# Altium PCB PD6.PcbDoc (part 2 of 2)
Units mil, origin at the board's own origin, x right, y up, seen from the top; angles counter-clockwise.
Board outline 8543.31 x 5314.96 mil, 4 copper layers (Top Layer, VBAT Plane, GND Plane, Bottom Layer), stack 62.8 mil thick; 258 components, 142 nets, 690 pads, 87 vias.
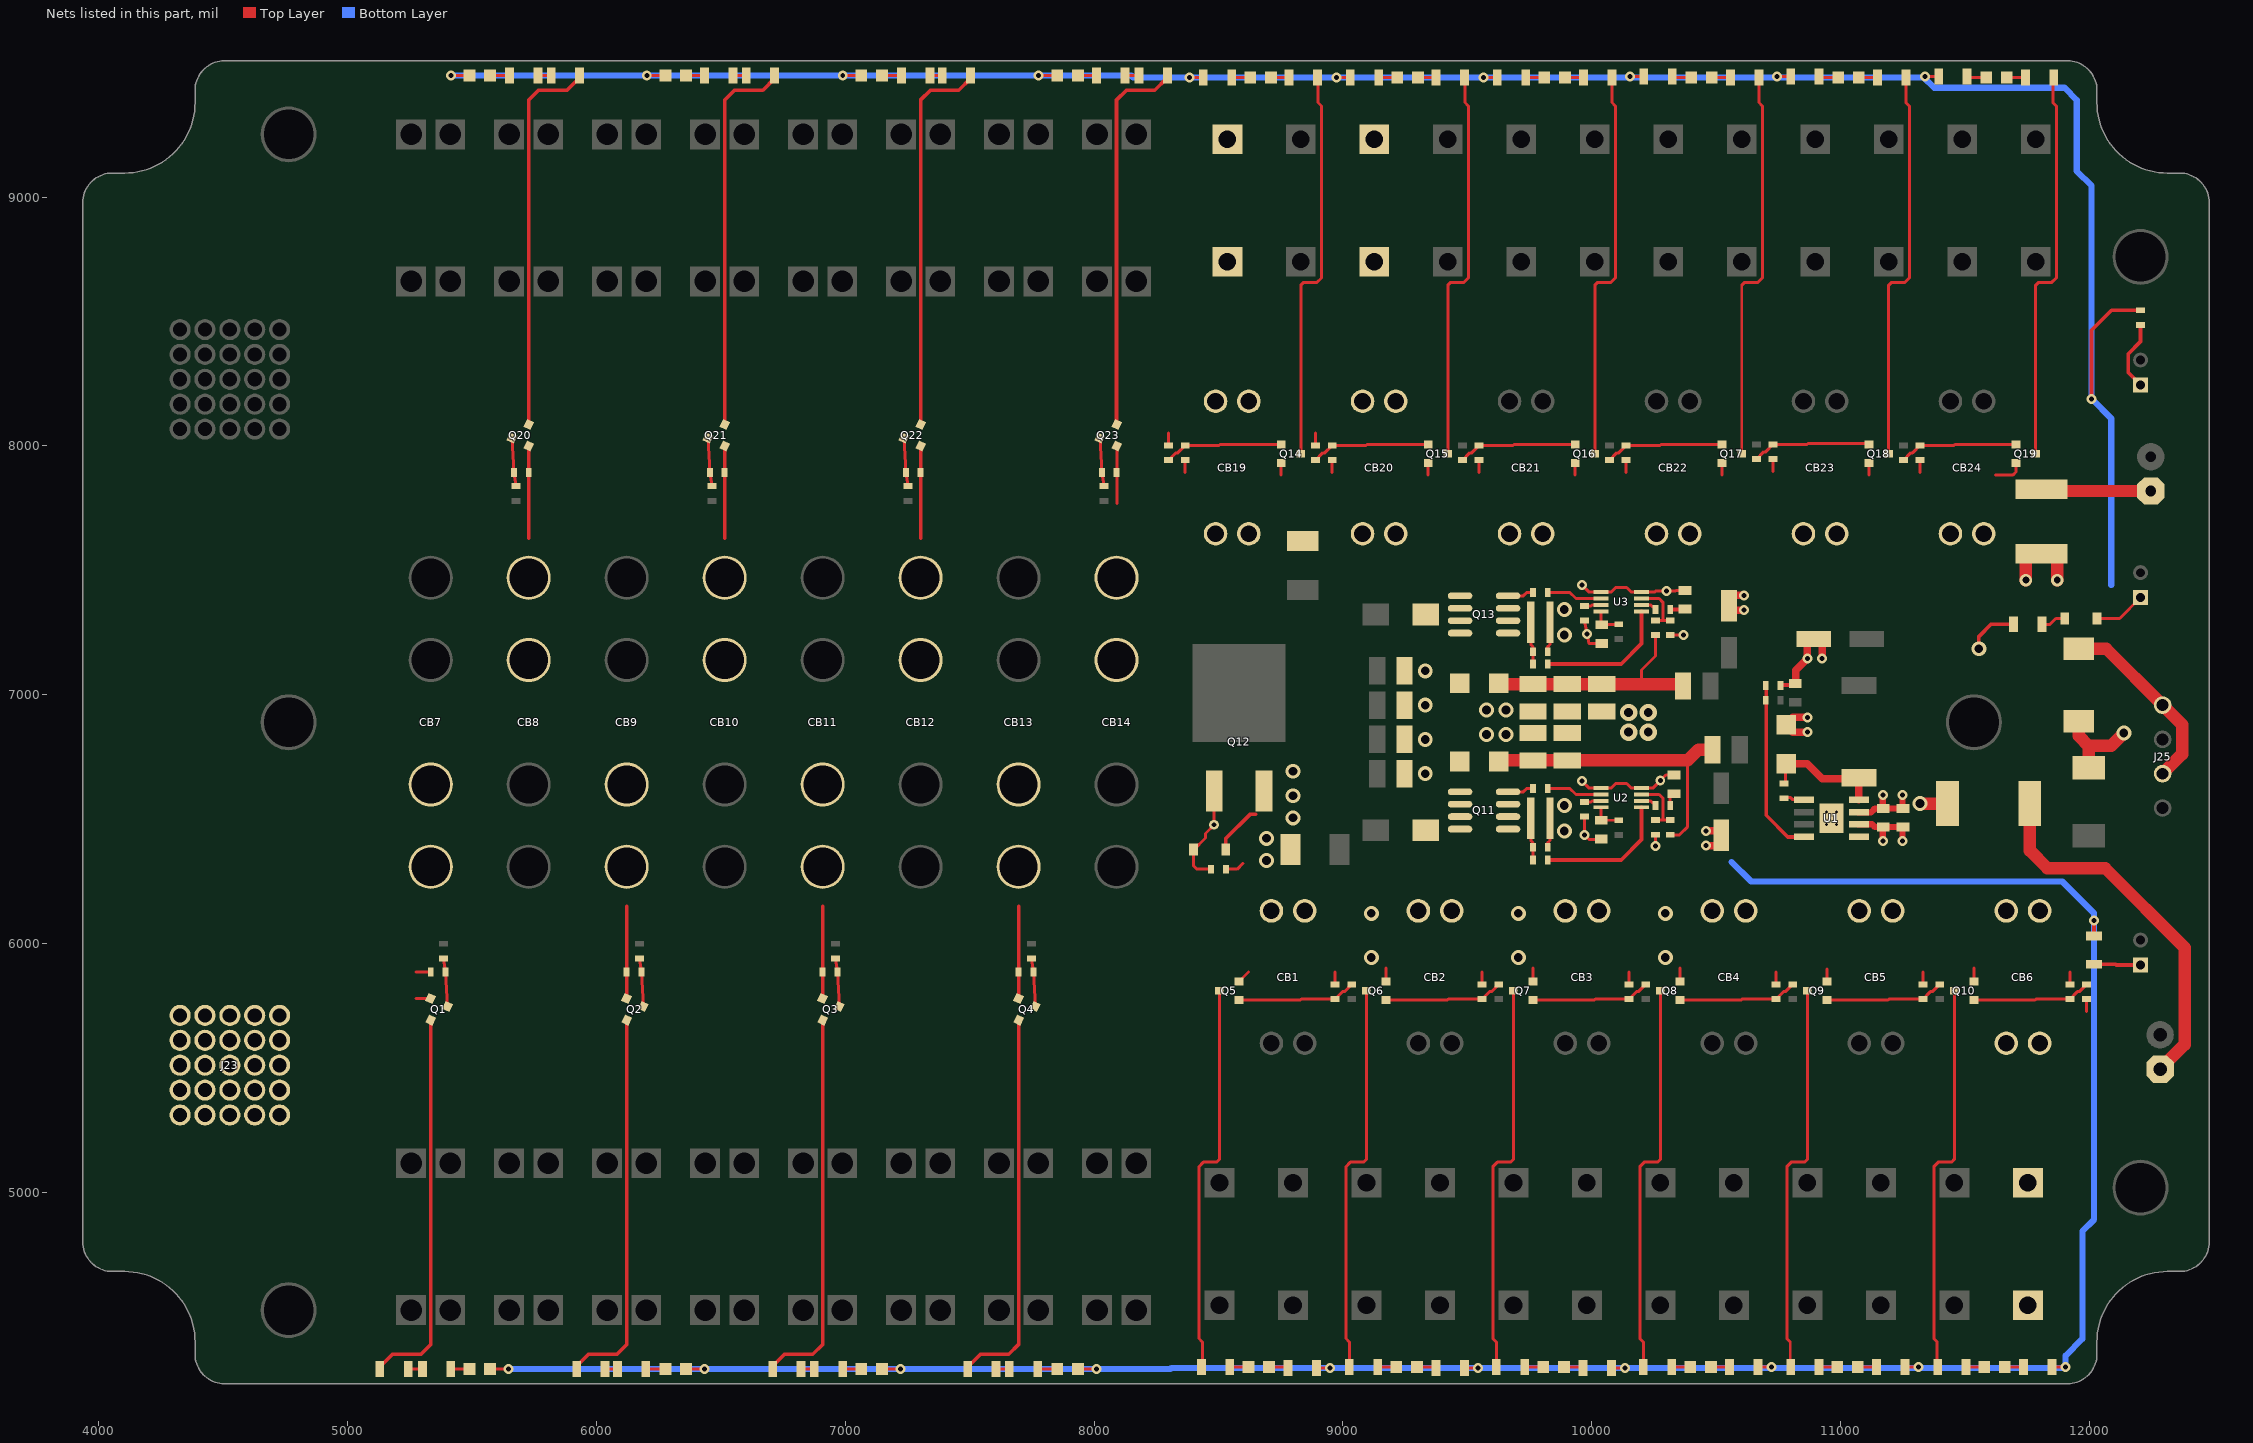
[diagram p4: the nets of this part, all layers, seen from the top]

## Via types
v1: diameter 40, hole 20, Top Layer to Bottom Layer, 47 vias
v2: diameter 60, hole 35, Top Layer to Bottom Layer, 32 vias
v3: diameter 70, hole 35, Top Layer to Bottom Layer, 4 vias
v4: diameter 50, hole 27.99, Top Layer to Bottom Layer, 4 vias

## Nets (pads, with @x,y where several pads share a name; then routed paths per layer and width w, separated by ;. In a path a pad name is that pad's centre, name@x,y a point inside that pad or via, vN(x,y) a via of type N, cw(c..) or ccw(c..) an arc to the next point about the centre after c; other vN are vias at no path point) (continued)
LOWCURRENTOUT_5_2: CB20.2 J39.1 R94.2 | length 49.2
  Top Layer w12: R94.2@8889.76,8001.97 8889.76,8051.18
LOWCURRENTOUT_6_1: CB6.2 J22.1 R101.2 | length 49.2
  Top Layer w12: 11988.19,5728.35 R101.2@11988.19,5777.56
LOWCURRENTOUT_6_2: CB19.2 J37.1 R95.2 | length 49.2
  Top Layer w12: R95.2@8299.21,8001.97 8299.21,8051.18
NetC3_2: C3.2 Q11.S R32.2 R33.2 | length 171
  Top Layer w12: R32.2@9754.92,6503.94 9754.92,6414.37 9763.78,6405.51 C3.2@9763.78,6387.8 R33.2@9763.78,6336.61
NetC4_2: C4.2 R34.1 U2.8 | length 114.2
  Top Layer w12: C4.2@10036.42,6500.98 U2.8@10036.42,6548.23 ; C4.2@10041.34,6496.06 R34.1@10108.27,6496.06
NetC5_1: C5.1 U1.1 | length 89.9
  Top Layer w12: C5.1@10767.72,6586.61 10771.65,6586.61 10799.21,6586.61 10807.09,6578.74 10852.83,6578.74 U1.1@10854.33,6578.74
NetC5_2: C5.2 D13.K L2.1 U1.8 | length 472.9
  Top Layer w12: C5.2@10777.56,6643.7 D13.K@10777.56,6712.6
  Top Layer w25: D13.K@10777.56,6722.44 D13.K@10781.5,6722.44
  Top Layer w30: D13.K@10781.5,6722.44 10866.14,6722.44 10925.2,6663.39 11072.83,6663.39 U1.8@11072.83,6579.13
NetC6_2: C6.2 R37.1 | length 49.9
  Top Layer w12: R37.1@10314.96,6555.12 10314.96,6602.6 10314.96,6604.96 C6.2@10315,6605
NetC8_2: C8.2 C9.2 D12.K L5.1 R40.2 | length 1217
  Top Layer w12: R40.2@10314.8,6437.64 10352.64,6437.64 10385,6470 10385,6736.34
  Top Layer w50: D12.K@9625.98,6736.34 C8.2@9763.78,6736.34 C9.2@9901.57,6736.34 10385,6736.34 10428.66,6780 L5.1@10475,6780
NetC17_2: C17.2 R47.2 U3.8 | length 114.2
  Top Layer w12: C17.2@10036.42,7288.39 U3.8@10036.42,7335.63 ; C17.2@10041.34,7283.46 R47.2@10108.27,7283.46
NetC19_2: C19.2 Q13.S R44.2 R46.2 | length 171
  Top Layer w12: R46.2@9754.92,7291.34 9754.92,7201.77 9763.78,7192.91 C19.2@9763.78,7173.23 R44.2@9763.78,7124.02
NetC20_2: C20.2 R49.1 | length 57.1
  Top Layer w15: R49.1@10314.96,7342.52 C20.2@10372.05,7342.52
NetCB16_2: CB16.2 J24.1 | length 1501.4
  Top Layer w50: CB16.2@11759.84,6562.99 11759.84,6374.02 11830.71,6303.15 12062.99,6303.15 12381.89,5984.25 12381.89,5594.49 J24.1@12283.46,5496.06
NetCB17_2: CB17.2 J25.2 J25.4 | length 771.2
  Top Layer w50: CB17.2@11956.69,7185.04 12066.93,7185.04 J25.4@12293.31,6958.66 12372.05,6879.92 12372.05,6761.81 J25.2@12293.31,6683.07
NetCB25_2: CB25.2 J26.1 | length 442.2
  Top Layer w50: CB25.2@11807.09,7826.77 11814.96,7818.9 J26.1@12246.06,7818.9
NetD1_A: D1.A R2.2 | length 84.6
  Top Layer w12: R2.2@5411.42,4291.34 R2.2@5415.35,4291.34 D1.A@5496.06,4291.34
NetD2_A: D2.A R4.2 | length 84.6
  Top Layer w12: R4.2@6198.82,4291.34 D2.A@6283.46,4291.34
NetD3_A: D3.A R6.2 | length 84.6
  Top Layer w12: R6.2@6986.22,4291.34 R6.2@6990.16,4291.34 D3.A@7070.87,4291.34
NetD4_A: D4.A R8.2 | length 84.6
  Top Layer w12: R8.2@7773.62,4291.34 D4.A@7858.27,4291.34
NetD5_A: D5.A R9.2 | length 76.8
  Top Layer w12: R9.2@8549.21,4299.21 D5.A@8625.98,4299.21
NetD5_K: D5.K R10.1 | length 82.7
  Top Layer w12: D5.K@8696.85,4299.21 R10.1@8779.53,4299.21
NetD6_A: D6.A R11.2 | length 80.7
  Top Layer w12: R11.2@9139.76,4299.21 D6.A@9220.47,4299.21
NetD6_K: D6.K R12.1 | length 78.7
  Top Layer w12: D6.K@9291.34,4299.21 R12.1@9370.08,4299.21
NetD7_A: D7.A R13.2 | length 80.7
  Top Layer w12: R13.2@9730.32,4299.21 D7.A@9811.02,4299.21
NetD7_K: D7.K R14.1 | length 78.7
  Top Layer w12: D7.K@9881.89,4299.21 R14.1@9960.63,4299.21
NetD8_A: D8.A R15.2 | length 80.7
  Top Layer w12: R15.2@10320.87,4299.21 D8.A@10401.57,4299.21
NetD8_K: D8.K R16.1 | length 78.7
  Top Layer w12: D8.K@10472.44,4299.21 R16.1@10551.18,4299.21
NetD9_A: D9.A R17.2 | length 80.7
  Top Layer w12: R17.2@10911.42,4299.21 R17.2@10913.39,4299.21 D9.A@10992.13,4299.21
NetD9_K: D9.K R18.1 | length 78.7
  Top Layer w12: D9.K@11062.99,4299.21 R18.1@11141.73,4299.21
NetD10_A: D10.A R19.2 | length 80.7
  Top Layer w12: R19.2@11501.97,4299.21 R19.2@11503.94,4299.21 D10.A@11582.68,4299.21
NetD10_K: D10.K R20.1 | length 78.7
  Top Layer w12: D10.K@11653.54,4299.21 R20.1@11732.28,4299.21
NetD11_K: D11.K R21.2 | length 188.1
  Top Layer w15: R21.2@12017.72,5917.32 12104.33,5917.32 12107.09,5914.57 D11.K@12204.72,5914.57
NetD12_A: D12.A L1.1 Q11.D
NetD14_K: D14.K D16.K | length 210.4
  Top Layer w12: D16.K@12029.06,7307.09 12120.87,7307.09 D14.K@12204.72,7390.94
NetD15_A: D15.A L3.1 Q13.D
NetD16_A: D16.A R35.2 | length 100.8
  Top Layer w12: R35.2@11809.06,7283.46 11840.55,7283.46 11864.17,7307.09 D16.A@11900.08,7307.09
NetD17_K: D17.K R61.2 | length 282.1
  Top Layer w15: D17.K@12204.72,8245.28 12155,8295 12155,8370 12204.72,8419.72 R61.2@12204.72,8486.22
NetD18_A: D18.A R62.2 | length 84.6
  Top Layer w12: D18.A@5566.93,9488.19 R62.2@5651.57,9488.19
NetD19_A: D19.A R64.2 | length 84.6
  Top Layer w12: D19.A@6354.33,9488.19 R64.2@6435.04,9488.19 R64.2@6438.98,9488.19
NetD20_A: D20.A R66.2 | length 84.6
  Top Layer w12: D20.A@7141.73,9488.19 R66.2@7226.38,9488.19
NetD21_A: D21.A R68.2 | length 84.6
  Top Layer w12: D21.A@7929.13,9488.19 R68.2@8009.84,9488.19 R68.2@8013.78,9488.19
NetD22_A: D22.A R71.2 | length 80.7
  Top Layer w12: D22.A@8704.72,9480.32 R71.2@8783.46,9480.31 R71.2@8785.43,9480.32
NetD22_K: D22.K R70.1 | length 78.7
  Top Layer w12: R70.1@8555.12,9480.32 D22.K@8633.86,9480.32
NetD23_A: D23.A R73.2 | length 80.7
  Top Layer w12: D23.A@9295.28,9480.32 R73.2@9374.02,9480.31 R73.2@9375.98,9480.32
NetD23_K: D23.K R72.1 | length 78.7
  Top Layer w12: R72.1@9145.67,9480.32 D23.K@9224.41,9480.32
NetD24_A: D24.A R75.2 | length 80.7
  Top Layer w12: D24.A@9885.83,9480.32 R75.2@9966.54,9480.31
NetD24_K: D24.K R74.1 | length 78.7
  Top Layer w12: R74.1@9736.22,9480.32 D24.K@9814.96,9480.32
NetD25_A: D25.A R77.2 | length 80.7
  Top Layer w12: D25.A@10476.38,9480.32 R77.2@10557.09,9480.32
NetD25_K: D25.K R76.1 | length 78.7
  Top Layer w12: R76.1@10326.77,9480.32 D25.K@10405.51,9480.32
NetD26_A: D26.A R79.2 | length 80.7
  Top Layer w12: D26.A@11066.93,9480.32 R79.2@11147.64,9480.31
NetD26_K: D26.K R78.1 | length 78.7
  Top Layer w12: R78.1@10917.32,9480.32 D26.K@10996.06,9480.32
NetD27_A: D27.A R81.2 | length 76.8
  Top Layer w12: D27.A@11661.42,9480.32 R81.2@11738.19,9480.32
NetD27_K: D27.K R80.1 | length 82.7
  Top Layer w12: R80.1@11507.87,9480.32 D27.K@11590.55,9480.32
NetD28_K: D28.K Q12.G R102.1 | length 411.8
  Top Layer w12: R102.1@8470.47,6299.21 8413.39,6299.21 8400.08,6312.52 D28.K@8400.08,6377.95 8447.32,6425.2 8447.32,6442.6 v1(8482.68,6477.95) Q12.G@8482.68,6614.17
NetQ1_D: Q1.D R1.1 | length 1539.6
  Top Layer w15: R1.1@5133.86,4303.15 5181.1,4350.39 5295.28,4350.39 5334.65,4389.76 Q1.D@5334.65,5692.67
NetQ1_G: Q1.G R22.2 R82.1 | length 193.5
  Top Layer w12: R82.1@5385.83,5940.94 R22.2@5393.7,5885.83 Q1.G@5401.82,5748.22
NetQ2_D: Q2.D R3.1 | length 1539.6
  Top Layer w15: R3.1@5921.26,4303.15 5968.5,4350.39 6082.68,4350.39 6122.05,4389.76 Q2.D@6122.05,5692.67
NetQ2_G: Q2.G R23.2 R83.1 | length 193.5
  Top Layer w12: R83.1@6173.23,5940.94 R23.2@6181.1,5885.83 Q2.G@6189.22,5748.22
NetQ3_D: Q3.D R5.1 | length 1539.6
  Top Layer w15: R5.1@6708.66,4303.15 6755.91,4350.39 6870.08,4350.39 6909.45,4389.76 Q3.D@6909.45,5692.67
NetQ3_G: Q3.G R24.2 R84.1 | length 193.5
  Top Layer w12: R84.1@6960.63,5940.94 R24.2@6968.5,5885.83 Q3.G@6976.62,5748.22
NetQ4_D: Q4.D R7.1 | length 1539.6
  Top Layer w15: R7.1@7496.06,4303.15 7543.31,4350.39 7657.48,4350.39 7696.85,4389.76 Q4.D@7696.85,5692.67
NetQ4_G: Q4.G R25.2 R85.1 | length 193.5
  Top Layer w12: R85.1@7748.03,5940.94 R25.2@7755.91,5885.83 Q4.G@7764.02,5748.22
NetQ5_D: Q5.D R9.1 | length 1582.9
  Top Layer w12: R9.1@8431.1,4299.21 8435.04,4299.21 8435.04,4399.61 8421.26,4413.39 8421.26,5104.33 8438.98,5122.05 8492.13,5122.05 8503.94,5133.86 Q5.D@8503.94,5807.09
NetQ5_G: Q5.G R26.2 R96.1 | length 478.8
  Top Layer w12: Q5.G@8582.68,5773.62 8828.74,5773.62 8832.68,5777.56 R26.2@8968.5,5777.56 8998.03,5807.09 9005.91,5807.09 R96.1@9035.43,5836.61
NetQ6_D: Q6.D R11.1 | length 1579
  Top Layer w12: R11.1@9025.59,4299.21 9025.59,4399.61 9011.81,4413.39 9011.81,5104.33 9029.53,5122.05 9082.68,5122.05 9094.49,5133.86 Q6.D@9094.49,5807.09
NetQ6_G: Q6.G R27.2 R97.1 | length 478.8
  Top Layer w12: Q6.G@9173.23,5773.62 9419.29,5773.62 9423.23,5777.56 R27.2@9559.06,5777.56 9588.58,5807.09 9596.46,5807.09 R97.1@9625.98,5836.61
NetQ7_D: Q7.D R13.1 | length 1579
  Top Layer w12: R13.1@9616.14,4299.21 9616.14,4399.61 9602.36,4413.39 9602.36,5104.33 9620.08,5122.05 9673.23,5122.05 9685.04,5133.86 Q7.D@9685.04,5807.09
NetQ7_G: Q7.G R28.2 R98.1 | length 478.8
  Top Layer w12: Q7.G@9763.78,5773.62 10009.84,5773.62 10013.78,5777.56 R28.2@10149.61,5777.56 10179.13,5807.09 10187.01,5807.09 R98.1@10216.54,5836.61
NetQ8_D: Q8.D R15.1 | length 1579
  Top Layer w12: R15.1@10206.69,4299.21 10206.69,4399.61 10192.91,4413.39 10192.91,5104.33 10210.63,5122.05 10263.78,5122.05 10275.59,5133.86 Q8.D@10275.59,5807.09
NetQ8_G: Q8.G R29.2 R99.1 | length 478.8
  Top Layer w12: Q8.G@10354.33,5773.62 10600.39,5773.62 10604.33,5777.56 R29.2@10740.16,5777.56 10769.68,5807.09 10777.56,5807.09 R99.1@10807.09,5836.61
NetQ9_D: Q9.D R17.1 | length 1579
  Top Layer w12: R17.1@10797.24,4299.21 10797.24,4399.61 10783.46,4413.39 10783.46,5104.33 10801.18,5122.05 10854.33,5122.05 10866.14,5133.86 Q9.D@10866.14,5807.09
NetQ9_G: Q9.G R30.2 R100.1 | length 478.8
  Top Layer w12: Q9.G@10944.88,5773.62 11190.94,5773.62 11194.88,5777.56 R30.2@11330.71,5777.56 11360.24,5807.09 11368.11,5807.09 R100.1@11397.64,5836.61
NetQ10_D: Q10.D R19.1 | length 1579
  Top Layer w12: R19.1@11387.8,4299.21 11387.8,4399.61 11374.02,4413.39 11374.02,5104.33 11391.73,5122.05 11444.88,5122.05 11456.69,5133.86 Q10.D@11456.69,5807.09
NetQ10_G: Q10.G R31.2 R101.1 | length 478.8
  Top Layer w12: Q10.G@11535.43,5773.62 11781.5,5773.62 11785.43,5777.56 R31.2@11921.26,5777.56 11950.79,5807.09 11958.66,5807.09 R101.1@11988.19,5836.61
NetQ11_G: Q11.G R38.2 | length 106
  Top Layer w12: Q11.G@9663.39,6610.43 9724.61,6610.43 9738.19,6624.02 R38.2@9763.78,6624.02
NetQ13_G: Q13.G R50.2 | length 106
  Top Layer w12: Q13.G@9663.39,7397.83 9724.61,7397.83 9738.19,7411.42 R50.2@9763.78,7411.42
NetQ14_D: Q14.D R71.1 | length 1579
  Top Layer w12: Q14.D@8830.71,7972.44 8830.71,8645.67 8842.52,8657.48 8895.67,8657.48 8913.39,8675.2 8913.39,9366.14 8899.61,9379.92 R71.1@8899.61,9480.31
NetQ14_G: Q14.G R55.2 R95.1 | length 478.8
  Top Layer w12: R95.1@8299.21,7942.91 8328.74,7972.44 8336.61,7972.44 R55.2@8366.14,8001.97 8501.97,8001.97 8505.91,8005.91 Q14.G@8751.97,8005.91
NetQ15_D: Q15.D R73.1 | length 1579
  Top Layer w12: Q15.D@9421.26,7972.44 9421.26,8645.67 9433.07,8657.48 9486.22,8657.48 9503.94,8675.2 9503.94,9366.14 9490.16,9379.92 R73.1@9490.16,9480.31
NetQ15_G: Q15.G R56.2 R94.1 | length 478.8
  Top Layer w12: R94.1@8889.76,7942.91 8919.29,7972.44 8927.17,7972.44 R56.2@8956.69,8001.97 9092.52,8001.97 9096.46,8005.91 Q15.G@9342.52,8005.91
NetQ16_D: Q16.D R75.1 | length 1579
  Top Layer w12: Q16.D@10011.81,7972.44 10011.81,8645.67 10023.62,8657.48 10076.77,8657.48 10094.49,8675.2 10094.49,9366.14 10080.71,9379.92 R75.1@10080.71,9480.31
NetQ16_G: Q16.G R57.2 R93.1 | length 478.8
  Top Layer w12: R93.1@9480.32,7942.91 9509.84,7972.44 9517.72,7972.44 R57.2@9547.24,8001.97 9683.07,8001.97 9687.01,8005.91 Q16.G@9933.07,8005.91
NetQ17_D: Q17.D R77.1 | length 1579
  Top Layer w12: Q17.D@10602.36,7972.44 10602.36,8645.67 10614.17,8657.48 10667.32,8657.48 10685.04,8675.2 10685.04,9366.14 10671.26,9379.92 R77.1@10671.26,9480.32
NetQ17_G: Q17.G R58.2 R92.1 | length 478.8
  Top Layer w12: R92.1@10070.87,7942.91 10100.39,7972.44 10108.27,7972.44 R58.2@10137.8,8001.97 10273.62,8001.97 10277.56,8005.91 Q17.G@10523.62,8005.91
NetQ18_D: Q18.D R79.1 | length 1579
  Top Layer w12: Q18.D@11192.91,7972.44 11192.91,8645.67 11204.72,8657.48 11257.87,8657.48 11275.59,8675.2 11275.59,9366.14 11261.81,9379.92 R79.1@11261.81,9480.31
NetQ18_G: Q18.G R59.2 R91.1 | length 478.8
  Top Layer w12: R91.1@10661.42,7946.85 10690.94,7976.38 10698.82,7976.38 R59.2@10728.35,8005.91 10864.17,8005.91 10868.11,8009.84 Q18.G@11114.17,8009.84
NetQ19_D: Q19.D R81.1 | length 1582.9
  Top Layer w12: Q19.D@11783.46,7972.44 11783.46,8645.67 11795.28,8657.48 11848.43,8657.48 11866.14,8675.2 11866.14,9366.14 11852.36,9379.92 11852.36,9480.31 R81.1@11856.3,9480.32
NetQ19_G: Q19.G R60.2 R90.1 | length 478.8
  Top Layer w12: R90.1@11251.97,7942.91 11281.5,7972.44 11289.37,7972.44 R60.2@11318.9,8001.97 11454.72,8001.97 11458.66,8005.91 Q19.G@11704.72,8005.91
NetQ20_D: Q20.D R63.1 | length 1539.6
  Top Layer w15: Q20.D@5728.35,8086.86 5728.35,9389.76 5767.72,9429.13 5881.89,9429.13 R63.1@5929.13,9476.38
NetQ20_G: Q20.G R51.2 R89.1 | length 193.5
  Top Layer w12: Q20.G@5661.17,8031.31 R51.2@5669.29,7893.7 R89.1@5677.17,7838.58
NetQ21_D: Q21.D R65.1 | length 1539.6
  Top Layer w15: Q21.D@6515.75,8086.86 6515.75,9389.76 6555.12,9429.13 6669.29,9429.13 R65.1@6716.54,9476.38
NetQ21_G: Q21.G R52.2 R88.1 | length 193.5
  Top Layer w12: Q21.G@6448.57,8031.31 R52.2@6456.69,7893.7 R88.1@6464.57,7838.58
NetQ22_D: Q22.D R67.1 | length 1539.6
  Top Layer w15: Q22.D@7303.15,8086.86 7303.15,9389.76 7342.52,9429.13 7456.69,9429.13 R67.1@7503.94,9476.38
NetQ22_G: Q22.G R53.2 R87.1 | length 193.5
  Top Layer w12: Q22.G@7235.98,8031.31 R53.2@7244.09,7893.7 R87.1@7251.97,7838.58
NetQ23_D: Q23.D R69.1 | length 1539.6
  Top Layer w15: Q23.D@8090.55,8086.86 8090.55,9389.76 8129.92,9429.13 8244.09,9429.13 R69.1@8291.34,9476.38
NetQ23_G: Q23.G R54.2 R86.1 | length 193.5
  Top Layer w12: Q23.G@8023.38,8031.31 R54.2@8031.5,7893.7 R86.1@8039.37,7838.58
NetR1_2: R1.2 R2.1 | length 53.1
  Top Layer w12: R1.2@5244.09,4291.34 R2.1@5297.24,4291.34
NetR3_2: R3.2 R4.1 | length 53.1
  Top Layer w12: R3.2@6031.5,4291.34 R3.2@6035.43,4291.34 R4.1@6084.65,4291.34
NetR5_2: R5.2 R6.1 | length 53.1
  Top Layer w12: R5.2@6818.9,4291.34 R5.2@6822.83,4291.34 R6.1@6872.05,4291.34
NetR7_2: R7.2 R8.1 | length 53.1
  Top Layer w12: R7.2@7606.3,4291.34 R8.1@7659.45,4291.34
NetR33_1: R33.1 U2.1 | length 540.7
  Top Layer w15: R33.1@9822.83,6336.61 10118.11,6336.61 10199.8,6418.31 U2.1@10199.8,6548.23
NetR36_2: R36.2 U2.7 | length 67.6
  Top Layer w12: R36.2@9970.47,6569.88 9997.05,6569.88 10000.98,6573.82 U2.7@10036.42,6573.82
NetR37_2: R37.2 U2.2 | length 63.8
  Top Layer w12: U2.2@10199.8,6573.82 10237.2,6573.82 R37.2@10255.91,6555.12
NetR38_1: R38.1 U2.6 | length 223.8
  Top Layer w12: R38.1@9822.83,6624.02 9911.42,6624.02 9936.02,6599.41 U2.6@10036.42,6599.41
NetR39_2: R39.2 R40.1 U2.3 | length 238.5
  Top Layer w12: U2.3@10199.8,6599.41 10270.59,6599.41 10285,6585 10285,6496.69 ; R39.2@10255.75,6496.69 10285,6496.69 ; R40.1@10314.8,6496.69 10285,6496.69
NetR41_1: R41.1 R42.2 U3.3 | length 223.6
  Top Layer w12: U3.3@10199.8,7386.81 10270.67,7386.81 10285.43,7372.05 10285.43,7299.21 ; R41.1@10255.91,7299.21 10285.43,7299.21 ; R42.2@10314.96,7299.21 10285.43,7299.21
NetR43_1: R43.1 R45.2 U1.4 | length 709.1
  Top Layer w15: R45.2@10700.79,7035.43 10700.79,6978.35 10700.79,6515.75 10787.4,6429.13 U1.4@10852.83,6429.13 U1.4@10854.33,6429.13
NetR44_1: R44.1 U3.1 | length 540.7
  Top Layer w15: R44.1@9822.83,7124.02 10118.11,7124.02 10199.8,7205.71 U3.1@10199.8,7335.63
NetR48_2: R48.2 U3.7 | length 67.6
  Top Layer w12: R48.2@9970.47,7357.28 9997.05,7357.28 10000.98,7361.22 U3.7@10036.42,7361.22
NetR49_2: R49.2 U3.2 | length 63.8
  Top Layer w12: U3.2@10199.8,7361.22 10237.2,7361.22 R49.2@10255.91,7342.52
NetR50_1: R50.1 U3.6 | length 223.8
  Top Layer w12: R50.1@9822.83,7411.42 9911.42,7411.42 9936.02,7386.81 U3.6@10036.42,7386.81
NetR62_1: R62.1 R63.2 | length 53.1
  Top Layer w12: R62.1@5765.75,9488.19 R63.2@5818.9,9488.19
NetR64_1: R64.1 R65.2 | length 53.1
  Top Layer w12: R64.1@6553.15,9488.19 R65.2@6602.36,9488.19 R65.2@6606.3,9488.19
NetR66_1: R66.1 R67.2 | length 53.1
  Top Layer w12: R66.1@7340.55,9488.19 R67.2@7389.76,9488.19 R67.2@7393.7,9488.19
NetR68_1: R68.1 R69.2 | length 53.1
  Top Layer w12: R68.1@8127.95,9488.19 R69.2@8181.1,9488.19
NetU1_5: U1.5
"OUTPUT VOLTAGE": C11.2 C12.2 C14.2 D15.K L4.1 R41.2 | length 954.9
  Top Layer w12: 10200,7043.19 10200,7100 10255.91,7155.91 R41.2@10255.91,7240.16
  Top Layer w50: D15.K@9625.98,7043.19 C14.2@9763.78,7043.19 C11.2@9901.57,7043.19 C12.2@10039.37,7043.19 10200,7043.19 10358.19,7043.19 10358.35,7043.35 L4.1@10360,7045
PSGND: C1.1 C2.1 C3.1 C4.1 C6.1 C7.1 C8.1 C9.1 C10.1 C11.1 C12.1 C13.1 C14.1 C15.1 C16.1 C17.1 C18.- C19.1 C20.1 C21.- C22.- CB16.1 CB17.1 CB25.1 D1.K D2.K D3.K D4.K D13.A D18.K D19.K D20.K D21.K D28.A D30.A Q12.S R10.2 R12.2 R14.2 R16.2 R18.2 R20.2 R21.1 R32.1 R35.1 R36.1 R39.1 R42.1 R45.1 R46.1 R48.1 R61.1 R70.2 R72.2 R74.2 R76.2 R78.2 R80.2 U1.6 U1.PAD U2.4 U2.5 U3.4 U3.5 | length 27983.5
  Top Layer w12: v1(5415.35,9488.19) D18.K@5490.16,9488.19 D18.K@5496.06,9488.19 ; D1.K@5566.93,4291.34 D1.K@5572.83,4291.34 v1(5647.64,4291.34) ; v1(6202.76,9488.19) D19.K@6277.56,9488.19 D19.K@6283.46,9488.19 ; D2.K@6354.33,4291.34 D2.K@6360.24,4291.34 v1(6435.04,4291.34) ; v1(6990.16,9488.19) D20.K@7064.96,9488.19 D20.K@7070.87,9488.19 ; D3.K@7141.73,4291.34 D3.K@7147.64,4291.34 v1(7222.44,4291.34) ; v1(7777.56,9488.19) D21.K@7852.36,9488.19 D21.K@7858.27,9488.19 ; D4.K@7929.13,4291.34 D4.K@7935.04,4291.34 v1(8009.84,4291.34) ; v1(8383.86,9480.32) R70.2@8437.01,9480.32 ; R70.2@8437.01,9488.19 R70.2@8437.01,9480.32 ; R70.2@8438.98,9480.31 R70.2@8437.01,9480.32 ; R10.2@8893.7,4295.28 R10.2@8897.64,4295.28 ; R10.2@8897.64,4287.4 R10.2@8897.64,4295.28 ; v1(8948.82,4295.28) R10.2@8897.64,4295.28 ; v1(8974.41,9480.31) R72.2@9027.56,9480.32 ; R72.2@9027.56,9488.19 R72.2@9027.56,9480.32 ; R72.2@9029.53,9480.31 R72.2@9027.56,9480.32 ; R12.2@9488.19,4287.4 R12.2@9488.19,4295.28 v1(9543.31,4295.28) ; v1(9564.96,9480.32) R74.2@9618.11,9480.32 ; R74.2@9618.11,9488.19 R74.2@9618.11,9480.32 ; R74.2@9620.08,9480.32 R74.2@9618.11,9480.32 ; C3.1@9822.83,6385.83 C3.1@9822.83,6387.8 9822.83,6405.51 9831.69,6414.37 R32.1@9831.69,6503.94 ; C19.1@9822.83,7173.23 9822.83,7192.91 9831.69,7201.77 R46.1@9831.69,7291.34 ; v1(9960.63,6653.54) 9989.17,6625 U2.5@10036.42,6625 10077.26,6625 10095.96,6643.7 10140.26,6643.7 10158.96,6625 U2.4@10199.8,6625 10245,6625 v1(10275,6655) 10297.4,6677.4 C6.1@10330,6677.4 ; v1(9960.63,7440.94) 9989.17,7412.4 U3.5@10036.42,7412.4 10077.26,7412.4 10095.96,7431.1 10140.26,7431.1 10158.96,7412.4 U3.4@10199.8,7412.4 10251.97,7412.4 10255.91,7416.34 v1(10300.2,7416.34) 10334.65,7416.34 10337.6,7419.29 C20.1@10374.02,7419.29 ; R36.1@9970.47,6510.83 v1(9970.47,6437.01) 9988.19,6419.29 10037.4,6419.29 C4.1@10039.37,6419.29 ; R48.1@9970.47,7298.23 v1(9980.32,7244.09) 9988.19,7206.69 C17.1@10039.37,7206.69 ; R14.2@10078.74,4287.4 R14.2@10078.74,4295.28 v1(10133.86,4295.28) ; v1(10153.54,9484.25) R76.2@10208.66,9484.25 R76.2@10208.66,9492.13 ; v1(10255.75,6392.36) R39.1@10255.75,6437.64 ; R42.1@10314.96,7240.16 v1(10369.09,7240.16) ; R16.2@10667.32,4299.21 R16.2@10669.29,4299.21 ; R16.2@10669.29,4291.34 R16.2@10669.29,4299.21 ; v1(10722.44,4299.21) R16.2@10669.29,4299.21 ; v1(10744.09,9484.25) R78.2@10799.21,9484.25 R78.2@10799.21,9492.13 ; R18.2@11257.87,4299.21 R18.2@11259.84,4299.21 ; R18.2@11259.84,4291.34 R18.2@11259.84,4299.21 ; v1(11312.99,4299.21) R18.2@11259.84,4299.21 ; v1(11338.58,9484.25) R80.2@11389.76,9484.25 ; R80.2@11389.76,9492.13 R80.2@11389.76,9484.25 ; R80.2@11393.7,9484.25 R80.2@11389.76,9484.25 ; R20.2@11848.43,4299.21 R20.2@11850.39,4299.21 ; R20.2@11850.39,4291.34 R20.2@11850.39,4299.21 ; v1(11903.54,4299.21) R20.2@11850.39,4299.21
  Top Layer w15: D28.A@8529.06,6377.95 8529.06,6422.49 8626.25,6519.69 8649.61,6519.69 ; R45.1@10759.84,7039.37 C15.1@10803.15,7039.37 ; v2(11555.12,7185.04) 11555.12,7234.25 11604.33,7283.46 R35.1@11694.88,7283.46 ; v1(12007.87,8188.98) 12007.87,8464.57 12088.58,8545.28 R61.1@12204.72,8545.28 ; R21.1@12017.72,6031.5 v1(12017.72,6092.52)
  Top Layer w25: U1.6@11070.87,6480.31 11072.83,6480.31 11125.98,6480.31 11137.8,6468.5 C1.1@11171.26,6468.5 11248.03,6468.5 v1(11248.03,6413.39) ; v1(11169.29,6413.39) C1.1@11169.29,6468.5
  Top Layer w30: v1(10458.86,6394.25) 10517.91,6394.25 C22.-@10533.68,6410.02 ; v1(10458.86,6453.31) 10517.91,6453.31 10527.85,6443.37 C22.-@10533.76,6437.46 ; C21.-@10553.27,7340.47 v1(10612.32,7340.47) ; C21.-@10553.27,7399.53 v1(10612.32,7399.53) ; D13.A@10787.4,6870.08 10807.09,6850.39 v1(10866.14,6850.39) ; D13.A@10787.4,6889.76 10807.09,6909.45 v1(10866.14,6909.45) ; C15.1@10818.9,7047.24 10818.9,7098.43 v1(10866.14,7145.67) C18.-@10866.14,7204.72 ; v1(10925.2,7145.67) C18.-@10925.2,7204.72
  Top Layer w50: v2(11318.9,6562.99) CB16.1@11429.13,6562.99 ; CB25.1@11742.13,7568.9 11744.09,7566.93 v4(11744.09,7460.63) ; v4(11870.08,7460.63) 11870.08,7566.93 CB25.1@11870.08,7568.9 ; CB17.1@11956.69,6893.7 11956.69,6834.65 11996.06,6795.28 ; D30.A@11996.06,6707.68 11996.06,6795.28 ; v2(12137.8,6846.46) 12086.61,6795.28 11996.06,6795.28
  Bottom Layer w25: v1(5415.35,9488.19) v1(6202.76,9488.19) v1(6990.16,9488.19) v1(7777.56,9488.19) 8149.61,9488.19 8157.48,9480.32 v1(8383.86,9480.32) ; v1(5647.64,4291.34) v1(6435.04,4291.34) v1(7222.44,4291.34) v1(8009.84,4291.34) 8307.09,4291.34 8311.02,4295.28 v1(8948.82,4295.28) v1(9543.31,4295.28) v1(10133.86,4295.28) ; 10561.02,6328.74 10639.76,6250 11889.76,6250 12017.72,6122.05 v1(12017.72,6092.52) 12017.72,4891.73 11970.96,4844.98 11970.96,4411.91 11903.54,4344.49 v1(11903.54,4299.21) 11899.61,4295.28 11312.99,4295.28 v1@10722.44,4295.28 ; 12086.61,7440.94 12086.61,8110.24 v1(12007.87,8188.98) 12007.87,9045.28 11948.82,9104.33 11948.82,9389.76 11899.61,9438.98 11375.98,9438.98 11334.65,9480.32 10744.09,9480.32 v1@10153.54,9480.32 ; v1(8383.86,9480.32) v1(8974.41,9480.31) ; v1(8383.86,9480.32) v1(8974.41,9480.31) ; v1(8383.86,9480.32) v1(8974.41,9480.31) ; v1(8383.86,9480.32) v1(8974.41,9480.31) ; v1(8974.41,9480.31) v1(9564.96,9480.32) ; v1(8974.41,9480.31) v1(9564.96,9480.32) ; v1(8974.41,9480.31) v1(9564.96,9480.32) ; v1(9564.96,9480.32) v1@10153.54,9480.32 ; v1(9564.96,9480.32) v1@10153.54,9480.32 ; v1(10133.86,4295.28) v1@10722.44,4295.28 ; v1(10133.86,4295.28) v1@10722.44,4295.28
  other v2: 9889.76,6452.76 8799.21,6505.91 9889.76,6555.12 8799.21,6594.49 9330.71,6683.07 8799.21,6692.91 9330.71,6820.87 9576.77,6840.55 9655.51,6840.55 9576.77,6938.98 9655.51,6938.98 9330.71,6958.66 9330.71,7096.46 9889.76,7240.16 9889.76,7342.52
  other v3: 10147.64,6850.39 10226.38,6850.39 10147.64,6929.13 10226.38,6929.13
VBAT: C1.2 C2.2 CB1.1 CB2.1 CB3.1 CB4.1 CB5.1 CB6.1 CB7.1 CB8.1 CB9.1 CB10.1 CB11.1 CB12.1 CB13.1 CB14.1 CB15.2 CB18.2 CB19.1 CB20.1 CB21.1 CB22.1 CB23.1 CB24.1 J23.PAD Q1.S Q2.S Q3.S Q4.S Q5.S Q6.S Q7.S Q8.S Q9.S Q10.S Q14.S Q15.S Q16.S Q17.S Q18.S Q19.S Q20.S Q21.S Q22.S Q23.S R22.1 R23.1 R24.1 R25.1 R26.1 R27.1 R28.1 R29.1 R30.1 R31.1 R51.1 R52.1 R53.1 R54.1 R55.1 R56.1 R57.1 R58.1 R59.1 R60.1 R102.2 U1.7 | length 4425.7
  Top Layer w12: 5275.28,5779.83 Q1.S@5334.03,5779.83 ; 5275.59,5885.83 R22.1@5334.65,5885.83 ; 8091.17,7768.34 8091.17,7893.7 Q23.S@8091.17,7999.69 ; 8366.14,7893.7 R55.1@8366.14,7942.91 ; R102.2@8529.53,6299.21 8574.8,6299.21 8598.43,6322.83 ; Q5.S@8582.68,5848.43 8620.26,5886.01 ; 8751.97,7883.86 Q14.S@8751.97,7931.1 Q14.S@8751.97,7935.04 ; 8956.69,7893.7 R56.1@8956.69,7942.91 ; R26.1@8968.5,5836.61 8968.5,5885.83 ; Q6.S@9173.23,5848.43 9173.23,5901.57 ; 9342.52,7883.86 Q15.S@9342.52,7931.1 Q15.S@9342.52,7935.04 ; 9547.24,7893.7 R57.1@9547.24,7942.91 ; R27.1@9559.06,5836.61 9559.06,5885.83 ; Q7.S@9763.78,5848.43 9763.78,5901.57 ; 9933.07,7883.86 Q16.S@9933.07,7931.1 Q16.S@9933.07,7935.04 ; 10137.8,7893.7 R58.1@10137.8,7942.91 ; R28.1@10149.61,5836.61 10149.61,5885.83 ; Q8.S@10354.33,5848.43 10354.33,5901.57 ; 10523.62,7883.86 Q17.S@10523.62,7931.1 Q17.S@10523.62,7935.04 ; 10728.35,7897.64 R59.1@10728.35,7946.85 ; R29.1@10740.16,5836.61 10740.16,5885.83 ; Q9.S@10944.88,5848.43 10944.88,5897.64 ; 11114.17,7883.86 Q18.S@11114.17,7931.1 Q18.S@11114.17,7935.04 ; 11318.9,7893.7 R60.1@11318.9,7942.91 ; R30.1@11330.71,5836.61 11330.71,5885.83 ; Q10.S@11535.43,5848.43 11535.43,5901.57 ; 11622.87,7883.86 11692.91,7883.86 11704.72,7895.67 Q19.S@11704.72,7931.1 Q19.S@11704.72,7935.04 ; R31.1@11921.26,5836.61 11921.26,5885.83
  Top Layer w15: 5728.35,7629.92 5728.35,7736.22 R51.1@5728.35,7893.7 Q20.S@5728.35,7999.69 ; Q2.S@6122.05,5779.53 6122.05,5779.83 R23.1@6122.05,5885.83 6122.05,6043.31 6122.05,6149.61 ; 6515.75,7629.92 R52.1@6515.75,7893.7 ; Q21.S@6515.75,7999.69 Q21.S@6515.75,7992.13 ; Q3.S@6909.45,5779.53 6909.45,5779.83 Q3.S@6909.45,5787.4 ; 6909.45,6149.61 R24.1@6909.45,5885.83 ; 7303.15,7629.92 7303.15,7736.22 R53.1@7303.15,7893.7 Q22.S@7303.15,7999.69 ; Q4.S@7696.85,5779.53 7696.85,5779.83 R25.1@7696.85,5885.83 7696.85,6043.31 7696.85,6149.61 ; R52.1@6515.75,7893.7 Q21.S@6515.75,7992.13 ; R52.1@6515.75,7893.7 Q21.S@6515.75,7992.13 ; Q3.S@6909.45,5787.4 R24.1@6909.45,5885.83 ; Q3.S@6909.45,5787.4 R24.1@6909.45,5885.83
  Top Layer w25: U1.7@11070.87,6527.56 11072.83,6527.56 11122.05,6527.56 11137.8,6543.31 C1.2@11171.26,6543.31 11248.03,6543.31 v1(11248.03,6598.43) ; C1.2@11169.29,6543.31 v1(11169.29,6598.43)
  other v2: 9114.17,5944.88 9704.72,5944.88 10295.28,5944.88 9114.17,6122.05 9704.72,6122.05 10295.28,6122.05 8692.91,6334.65 8692.91,6423.23
pads on no net: U1.2 U1.3

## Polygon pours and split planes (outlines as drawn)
VBAT on Top Layer "Top Layer-No Net" (solid, remove dead copper, pour order 1008): 8582.68,6259.84 11929.13,6259.84 11929.13,5870.08 8582.68,5870.08
VBAT on Top Layer "Top Layer-VBAT 1" (solid, remove dead copper, pour order 1007): 8257.87,7519.69 11669.29,7519.69 11669.29,7909.45 8257.87,7909.45 8257.87,7519.69
HIGHCURRENTOUT_3_2 on Top Layer "Top Layer-VBAT" (solid, remove dead copper, pour order 1020): 6338.58,7480.31 6338.58,7047.24 6299.21,7007.87 5944.88,7007.87 5905.51,7047.24 5905.51,7480.31 5748.03,7637.8 5748.03,8425.2 5905.51,8582.68 5905.51,9370.08 5944.88,9409.45 6299.21,9409.45 6338.58,9370.08 6338.58,8582.68 6496.06,8425.2 6496.06,7637.8
HIGHCURRENTOUT_2_2 on Top Layer "Top Layer-VBAT" (solid, remove dead copper, pour order 1019): 7125.98,7480.31 7125.98,7047.24 7086.61,7007.87 6732.28,7007.87 6692.91,7047.24 6692.91,7480.31 6535.43,7637.8 6535.43,8425.2 6692.91,8582.68 6692.91,9370.08 6732.28,9409.45 7086.61,9409.45 7125.98,9370.08 7125.98,8582.68 7283.46,8425.2 7283.46,7637.8
HIGHCURRENTOUT_1_2 on Top Layer "Top Layer-VBAT" (solid, remove dead copper, pour order 1018): 7913.39,7480.31 7913.39,7047.24 7874.02,7007.87 7519.69,7007.87 7480.31,7047.24 7480.31,7480.31 7322.83,7637.8 7322.83,8425.2 7480.31,8582.68 7480.31,9370.08 7519.69,9409.45 7874.02,9409.45 7913.39,9370.08 7913.39,8582.68 8070.87,8425.2 8070.87,7637.8
HIGHCURRENTOUT_4_2 on Top Layer "Top Layer-VBAT" (solid, remove dead copper, pour order 1014): 5551.18,7480.31 5551.18,7047.24 5511.81,7007.87 5157.48,7007.87 5118.11,7047.24 5118.11,7480.31 5039.37,7559.06 5039.37,8503.94 5118.11,8582.68 5118.11,9370.08 5157.48,9409.45 5511.81,9409.45 5551.18,9370.08 5551.18,8582.68 5708.66,8425.2 5708.66,7637.8
NetC3_2 on Top Layer "Top Layer-GND" (solid, remove dead copper, pour order 1000): 9566.93,6299.21 9734.25,6299.21 9734.25,6427.17 9812.99,6427.17 9812.99,6594.49 9606.3,6594.49 9566.93,6594.49
NetC19_2 on Top Layer "Top Layer-GND" (solid, remove dead copper, pour order 1002): 9566.93,7086.61 9734.25,7086.61 9734.25,7214.57 9812.99,7214.57 9812.99,7381.89 9606.3,7381.89 9566.93,7381.89
24_VIN on Top Layer "Top Layer-GND" (solid, remove dead copper, pour order 1001): 8858.27,7480.31 8858.27,6999.61 ccw(c8958.27,6999.61) 8958.27,6899.61 9183.07,6899.61 9183.07,7480.31
12_VIN on Top Layer "Top Layer-GND" (solid, remove dead copper, pour order 1003): 8858.27,6299.21 8858.27,6779.92 cw(c8958.27,6779.92) 8958.27,6879.92 9183.07,6879.92 9183.07,6299.21
HIGHCURRENTOUT_1_1 on Top Layer "Top Layer-VBAT" (solid, remove dead copper, pour order 1022): 5511.81,6299.21 5511.81,6732.28 5551.18,6771.65 5905.51,6771.65 5944.88,6732.28 5944.88,6299.21 6102.36,6141.73 6102.36,5354.33 5944.88,5196.85 5944.88,4409.45 5905.51,4370.08 5551.18,4370.08 5511.81,4409.45 5511.81,5196.85 5354.33,5354.33 5354.33,6141.73
HIGHCURRENTOUT_2_1 on Top Layer "Top Layer-VBAT" (solid, remove dead copper, pour order 1009): 6299.21,6299.21 6299.21,6732.28 6338.58,6771.65 6692.91,6771.65 6732.28,6732.28 6732.28,6299.21 6889.76,6141.73 6889.76,5354.33 6732.28,5196.85 6732.28,4409.45 6692.91,4370.08 6338.58,4370.08 6299.21,4409.45 6299.21,5196.85 6141.73,5354.33 6141.73,6141.73
HIGHCURRENTOUT_3_1 on Top Layer "Top Layer-VBAT" (solid, remove dead copper, pour order 1010): 7086.61,6299.21 7086.61,6732.28 7125.98,6771.65 7480.31,6771.65 7519.69,6732.28 7519.69,6299.21 7677.17,6141.73 7677.17,5354.33 7519.69,5196.85 7519.69,4409.45 7480.31,4370.08 7125.98,4370.08 7086.61,4409.45 7086.61,5196.85 6929.13,5354.33 6929.13,6141.73
HIGHCURRENTOUT_4_1 on Top Layer "Top Layer-VBAT" (solid, remove dead copper, pour order 1012): 7874.02,6299.21 7874.02,6732.28 7913.39,6771.65 8267.72,6771.65 8307.09,6732.28 8307.09,6299.21 8464.57,6141.73 8464.57,5354.33 8307.09,5196.85 8307.09,4409.45 8267.72,4370.08 7913.39,4370.08 7874.02,4409.45 7874.02,5196.85 7716.54,5354.33 7716.54,6141.73
VBAT on Top Layer "Top Layer-VBAT HP" (solid, remove dead copper, pour order 1023): 3838.58,7677.17 7913.39,7677.17 7913.39,7913.39 8257.87,7913.39 8257.87,6102.36 5511.81,6102.36 5511.81,4409.45 5000,4409.45 5000,4133.86 3838.58,4133.86
HIGHCURRENTOUT_2_1 on Bottom Layer "Top Layer-VBAT" (solid, remove dead copper, pour order 1004): 6299.21,6299.21 6299.21,6732.28 6338.58,6771.65 6692.91,6771.65 6732.28,6732.28 6732.28,6299.21 6889.76,6141.73 6889.76,5354.33 6732.28,5196.85 6732.28,5039.37 6692.91,5000 6338.58,5000 6299.21,5039.37 6299.21,5196.85 6141.73,5354.33 6141.73,6141.73
HIGHCURRENTOUT_3_1 on Bottom Layer "Top Layer-VBAT" (solid, remove dead copper, pour order 1006): 7086.61,6299.21 7086.61,6732.28 7125.98,6771.65 7480.31,6771.65 7519.69,6732.28 7519.69,6299.21 7677.17,6141.73 7677.17,5354.33 7519.69,5196.85 7519.69,5039.37 7480.31,5000 7125.98,5000 7086.61,5039.37 7086.61,5196.85 6929.13,5354.33 6929.13,6141.73
HIGHCURRENTOUT_4_1 on Bottom Layer "Top Layer-VBAT" (solid, remove dead copper, pour order 1011): 7874.02,6299.21 7874.02,6732.28 7913.39,6771.65 8267.72,6771.65 8307.09,6732.28 8307.09,6299.21 8464.57,6141.73 8464.57,5354.33 8307.09,5196.85 8307.09,5039.37 8267.72,5000 7913.39,5000 7874.02,5039.37 7874.02,5196.85 7716.54,5354.33 7716.54,6141.73
HIGHCURRENTOUT_4_2 on Bottom Layer "Top Layer-VBAT" (solid, remove dead copper, pour order 1013): 5551.18,7480.31 5551.18,7047.24 5511.81,7007.87 5157.48,7007.87 5118.11,7047.24 5118.11,7480.31 5039.37,7559.06 5039.37,8503.94 5118.11,8582.68 5118.11,8740.16 5157.48,8779.53 5511.81,8779.53 5551.18,8740.16 5551.18,8582.68 5708.66,8425.2 5708.66,7637.8
HIGHCURRENTOUT_3_2 on Bottom Layer "Top Layer-VBAT" (solid, remove dead copper, pour order 1015): 6338.58,7480.31 6338.58,7047.24 6299.21,7007.87 5944.88,7007.87 5905.51,7047.24 5905.51,7480.31 5748.03,7637.8 5748.03,8425.2 5905.51,8582.68 5905.51,8740.16 5944.88,8779.53 6299.21,8779.53 6338.58,8740.16 6338.58,8582.68 6496.06,8425.2 6496.06,7637.8
HIGHCURRENTOUT_2_2 on Bottom Layer "Top Layer-VBAT" (solid, remove dead copper, pour order 1016): 7125.98,7480.31 7125.98,7047.24 7086.61,7007.87 6732.28,7007.87 6692.91,7047.24 6692.91,7480.31 6535.43,7637.8 6535.43,8425.2 6692.91,8582.68 6692.91,8740.16 6732.28,8779.53 7086.61,8779.53 7125.98,8740.16 7125.98,8582.68 7283.46,8425.2 7283.46,7637.8
HIGHCURRENTOUT_1_2 on Bottom Layer "Top Layer-VBAT" (solid, remove dead copper, pour order 1017): 7913.39,7480.31 7913.39,7047.24 7874.02,7007.87 7519.69,7007.87 7480.31,7047.24 7480.31,7480.31 7322.83,7637.8 7322.83,8425.2 7480.31,8582.68 7480.31,8740.16 7519.69,8779.53 7874.02,8779.53 7913.39,8740.16 7913.39,8582.68 8070.87,8425.2 8070.87,7637.8
HIGHCURRENTOUT_1_1 on Bottom Layer "Top Layer-VBAT" (solid, remove dead copper, pour order 1021): 5511.81,6299.21 5511.81,6732.28 5551.18,6771.65 5905.51,6771.65 5944.88,6732.28 5944.88,6299.21 6102.36,6141.73 6102.36,5354.33 5944.88,5196.85 5944.88,5039.37 5905.51,5000 5551.18,5000 5511.81,5039.37 5511.81,5196.85 5354.33,5354.33 5354.33,6141.73
PSGND on Bottom Layer "PSGND-Bottom Layer" (solid, remove dead copper, pour order 1005): 8661.42,6299.21 8661.42,7047.24 8858.27,7244.09 8858.27,7480.31 12362.2,7480.31 12362.2,6299.21
GND on Bottom Layer "Bottom Layer-GND HP" (solid, remove dead copper, pour order 1021): 3897.64,9409.45 11929.13,9409.45 11929.13,4409.45 3897.64,4409.45
VBAT on VBAT Plane (split plane): 311 vertices, not listed, extent 3962.04,4257.32 12455.28,9522.21
GND on VBAT Plane (split plane): 4866.82,7928.46 4188.3,7928.46 4188.3,8606.97 4866.82,8606.97
GND on GND Plane (split plane): 311 vertices, not listed, extent 3962.04,4257.32 12455.28,9522.21
VBAT on GND Plane (split plane): 4866.82,5172.55 4188.3,5172.55 4188.3,5851.07 4866.82,5851.07

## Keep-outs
Keep-Out Layer:
  lines w6.89: 3937.01,4801.18 ccw(c4055.12,4801.18) 4055.12,4683.07 4104.33,4683.07 cw(c4104.33,4399.61) 4387.8,4399.61 4387.8,4350.39 ccw(c4505.91,4350.39) 4505.91,4232.28 11911.42,4232.28 ccw(c11911.42,4350.39) 12029.53,4350.39 12029.53,4399.61 cw(c12312.99,4399.61) 12312.99,4683.07 12362.2,4683.07 ccw(c12362.2,4801.18) 12480.31,4801.18 12480.31,8978.35 ccw(c12362.2,8978.35) 12362.2,9096.46 12312.99,9096.46 cw(c12312.99,9379.92) 12029.53,9379.92 12029.53,9429.13 ccw(c11911.42,9429.13) 11911.42,9547.24 4505.91,9547.24 ccw(c4505.91,9429.13) 4387.8,9429.13 4387.8,9379.92 cw(c4104.33,9379.92) 4104.33,9096.46 4055.12,9096.46 ccw(c4055.12,8978.35) 3937.01,8978.35 3937.01,6889.76 3937.01,4801.18

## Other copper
Top Layer:
  rectangle net VBAT: 8582.68,6305.12 8801.18,6452.76
  rectangle net PSGND: 8582.68,6466.54 8838.58,6732.28
  rectangle net PSGND: 9818.9,7208.66 9925.2,7374.02
  rectangle net PSGND: 9818.9,6421.26 9925.2,6586.61
  rectangle net LOWCURRENTOUT_6_1: 11555.12,4370.08 11948.82,5748.03
  rectangle net LOWCURRENTOUT_5_1: 10964.57,4370.08 11358.27,5748.03
  region net LOWCURRENTOUT_6_1: 12027.56,5748.03 11476.38,5748.03 11476.38,5137.8 12027.56,5137.8
  region net LOWCURRENTOUT_5_1: 11437.01,5748.03 10885.83,5748.03 10885.83,5137.8 11437.01,5137.8
  rectangle net LOWCURRENTOUT_1_1: 8602.36,4370.08 8996.06,5748.03
  rectangle net LOWCURRENTOUT_2_1: 9192.91,4370.08 9586.61,5748.03
  rectangle net LOWCURRENTOUT_3_1: 9783.46,4370.08 10177.17,5748.03
  rectangle net LOWCURRENTOUT_4_1: 10374.02,4370.08 10767.72,5748.03
  region net LOWCURRENTOUT_1_1: 9074.8,5748.03 8523.62,5748.03 8523.62,5137.8 9074.8,5137.8
  region net LOWCURRENTOUT_2_1: 9665.35,5748.03 9114.17,5748.03 9114.17,5137.8 9665.35,5137.8
  region net LOWCURRENTOUT_3_1: 10255.91,5748.03 9704.72,5748.03 9704.72,5137.8 10255.91,5137.8
  region net LOWCURRENTOUT_4_1: 10846.46,5748.03 10295.28,5748.03 10295.28,5137.8 10846.46,5137.8
  rectangle net GND: 4173.23,7913.39 4881.89,8622.05
  region net LOWCURRENTOUT_6_2: 8732.28,9409.45 8338.58,9409.45 8338.58,8031.5 8732.28,8031.5
  rectangle net LOWCURRENTOUT_6_2: 8259.84,8031.5 8811.02,8641.73
  region net LOWCURRENTOUT_5_2: 9322.83,9409.45 8929.13,9409.45 8929.13,8031.5 9322.83,8031.5
  rectangle net LOWCURRENTOUT_5_2: 8850.39,8031.5 9401.57,8641.73
  region net LOWCURRENTOUT_4_2: 9913.39,9409.45 9519.69,9409.45 9519.69,8031.5 9913.39,8031.5
  rectangle net LOWCURRENTOUT_4_2: 9440.94,8031.5 9992.13,8641.73
  region net LOWCURRENTOUT_3_2: 10503.94,9409.45 10110.24,9409.45 10110.24,8031.5 10503.94,8031.5
  rectangle net LOWCURRENTOUT_3_2: 10031.5,8031.5 10582.68,8641.73
  region net LOWCURRENTOUT_2_2: 11094.49,9409.45 10700.79,9409.45 10700.79,8031.5 11094.49,8031.5
  rectangle net LOWCURRENTOUT_2_2: 10622.05,8031.5 11173.23,8641.73
  region net LOWCURRENTOUT_1_2: 11685.04,9409.45 11291.34,9409.45 11291.34,8031.5 11685.04,8031.5
  rectangle net LOWCURRENTOUT_1_2: 11212.6,8031.5 11763.78,8641.73
  pour cut-out: 5354.33,5921.26 5362.2,5929.13 5314.96,5929.13 5314.96,5803.15 5303.15,5803.15 5303.15,5763.78 5354.33,5740.16
  pour cut-out: 5413.54,5962.76 5413.39,6019.69 5354.33,6019.69 5354.53,5962.76
  pour cut-out: 6200.94,5962.76 6200.79,6019.69 6141.73,6019.69 6141.93,5962.76
  pour cut-out: 6988.35,5962.76 6988.19,6019.69 6929.13,6019.69 6929.33,5962.76
  pour cut-out: 7775.75,5962.76 7775.59,6019.69 7716.54,6019.69 7716.73,5962.76
  pour cut-out: 8011.65,7816.77 8011.81,7759.84 8070.87,7759.84 8070.67,7816.77
  pour cut-out: 7224.25,7816.77 7224.41,7759.84 7283.46,7759.84 7283.27,7816.77
  pour cut-out: 5649.45,7816.77 5649.61,7759.84 5708.66,7759.84 5708.46,7816.77
  pour cut-out: 6436.85,7816.77 6437.01,7759.84 6496.06,7759.84 6495.87,7816.77
  pour cut-out: 8055.5,8072.62 8042.89,8012.22 8070.87,8017.9 8074.8,8070.87
  pour cut-out: 5693.3,8072.62 5680.68,8012.22 5708.66,8017.9 5712.6,8070.87
  pour cut-out: 6480.7,8072.62 6468.08,8012.22 6496.06,8017.9 6500,8070.87
  pour cut-out: 7268.1,8072.62 7255.49,8012.22 7283.46,8017.9 7287.4,8070.87
  pour cut-out: 7731.9,5706.9 7744.51,5767.31 7716.54,5761.63 7712.6,5708.66
  pour cut-out: 6944.5,5706.9 6957.11,5767.31 6929.13,5761.63 6925.2,5708.66
  pour cut-out: 6157.1,5706.9 6169.71,5767.31 6141.73,5761.63 6137.8,5708.66
  pour cut-out: 5369.69,5706.9 5382.31,5767.31 5381.89,5921.26 5350.39,5921.26 5350.39,5807.09 5303.15,5763.78 5322.83,5728.35 5350.39,5708.66
  region net GND: 8838.58,6742.13 8336.61,6742.13 8277.56,6801.18 8277.56,7480.31 8740.16,7480.31 8740.16,7362.2 8838.58,7263.78
  region net NetD12_A: 9389.76,6781.5 9566.93,6781.5 9566.93,6299.21 9212.6,6299.21 9212.6,6604.33 9320.87,6604.33 9389.76,6673.23
  region net NetD15_A: 9389.76,6998.03 9566.93,6998.03 9566.93,7480.31 9212.6,7480.31 9212.6,7175.2 9320.87,7175.2 9389.76,7106.3
  region net PSGND: 10285.43,6988.19 10511.81,6889.76 10285.43,6791.34
  region net PSGND: 9192.91,6889.76 9192.91,6614.17 9311.02,6614.17 9379.92,6683.07 9379.92,6791.34 10285.43,6791.34 10285.43,6889.76
  region net PSGND: 9192.91,6889.76 9192.91,7165.35 9311.02,7165.35 9379.92,7096.46 9379.92,6988.19 10285.43,6988.19 10285.43,6889.76
Bottom Layer:
  rectangle net LOWCURRENTOUT_6_1: 11555.12,4921.26 11948.82,5748.03
  rectangle net LOWCURRENTOUT_5_1: 10964.57,4921.26 11358.27,5748.03
  rectangle net LOWCURRENTOUT_1_1: 8602.36,4921.26 8996.06,5748.03
  rectangle net LOWCURRENTOUT_2_1: 9192.91,4921.26 9586.61,5748.03
  rectangle net LOWCURRENTOUT_3_1: 9783.46,4921.26 10177.17,5748.03
  rectangle net LOWCURRENTOUT_4_1: 10374.02,4921.26 10767.72,5748.03
  rectangle net VBAT: 4173.23,5157.48 4881.89,5866.14
  region net LOWCURRENTOUT_6_2: 8732.28,8858.27 8338.58,8858.27 8338.58,8031.5 8732.28,8031.5
  region net LOWCURRENTOUT_5_2: 9322.83,8858.27 8929.13,8858.27 8929.13,8031.5 9322.83,8031.5
  region net LOWCURRENTOUT_4_2: 9913.39,8858.27 9519.69,8858.27 9519.69,8031.5 9913.39,8031.5
  region net LOWCURRENTOUT_3_2: 10503.94,8858.27 10110.24,8858.27 10110.24,8031.5 10503.94,8031.5
  region net LOWCURRENTOUT_2_2: 11094.49,8858.27 10700.79,8858.27 10700.79,8031.5 11094.49,8031.5
  region net LOWCURRENTOUT_1_2: 11685.04,8858.27 11291.34,8858.27 11291.34,8031.5 11685.04,8031.5
  pour cut-out: 9946.85,6403.54 9946.85,6451.77 9953.74,6458.66 10171.26,6458.66 10171.26,6470.47 9944.88,6470.47 9934.06,6459.65 9934.06,6403.54
VBAT Plane (plane layer: these items are gaps in the copper):
  lines w30: 4173.23,7913.39 4881.89,7913.39 4881.89,8622.05 4173.23,8622.05 4173.23,7913.39
GND Plane (plane layer: these items are gaps in the copper):
  lines w30: 4173.23,5157.48 4173.23,5866.14 4881.89,5866.14 4881.89,5157.48 4173.23,5157.48

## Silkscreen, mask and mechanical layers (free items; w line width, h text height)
Top Overlay:
  lines w8: 5147.64,9478.35 5354.33,9478.35 ; 5324.8,9458.66 5354.33,9478.35 ; 5324.8,9498.03 5354.33,9478.35 ; 9035.43,6643.7 9074.8,6643.7 ; 9035.43,6663.39 9074.8,6663.39 ; 9035.43,6683.07 9074.8,6683.07 ; 9035.43,6702.76 9074.8,6702.76 ; 9035.43,6722.44 9074.8,6722.44 ; 9035.43,6781.5 9074.8,6781.5 ; 9035.43,6801.18 9074.8,6801.18 ; 9035.43,6820.87 9074.8,6820.87 ; 9035.43,6840.55 9074.8,6840.55 ; 9035.43,6860.24 9074.8,6860.24 ; 9035.43,6919.29 9074.8,6919.29 ; 9035.43,6938.98 9074.8,6938.98 ; 9035.43,6958.66 9074.8,6958.66 ; 9035.43,6978.35 9074.8,6978.35 ; 9035.43,6998.03 9074.8,6998.03 ; 9035.43,7057.09 9074.8,7057.09 ; 9035.43,7076.77 9074.8,7076.77 ; 9035.43,7096.46 9074.8,7096.46 ; 9035.43,7116.14 9074.8,7116.14 ; 9035.43,7135.83 9074.8,7135.83 ; 9980.32,7391.73 9990.16,7431.1
  lines w10: 10259.84,7433.07 10259.84,7393.7 10275.59,7377.95 ; 10342.52,6551.18 10362.2,6531.5 10362.2,6413.39
  text "D18-27" at 4881.89,9458.66 h45
  text "R62-81" at 4881.89,9399.61 h45
  text "VBATT-" at 4940.94,8503.94 h80 r270
  text "Rev 6" at 4242.13,7795.28 h80 r270
  text "Power Distribution Panel" at 4370.08,7795.28 h80 r270
  text "VBATT+" at 4940.94,5748.03 h80 r270
  text "EJVW" at 5511.81,5748.03 h50
  text "D1-10" at 4842.52,4350.39 h45
  text "R1-20" at 4842.52,4291.34 h45
Mechanical 1:
  drawing of 42 lines, arcs and shapes, not listed
  text "ATTENTION EARTHLINGS" at 17125.98,9842.52 h118.11
  text "CALIBRATE BLASTERS THUSLY" at 16929.13,7874.02 h118.11
Mechanical 13:
  lines w10: 8169.29,6889.76 8248.03,6889.76 ; 8208.66,6850.39 8208.66,6929.13
Drill Drawing:
  text "All Drill Dimensions are Finished Hole Size" at 17125.98,9724.41 h50
  text "STACKUP" at 14901.57,8622.05 h50
  text "1 oz Cu" at 14901.57,8543.31 h50
  text "3 oz Cu" at 14901.57,8385.83 h50
  text "3 oz Cu" at 14901.57,8228.35 h50
  text "1 oz Cu" at 14901.57,8070.87 h50
  text ".Legend" at 16929.13,8070.87 h50

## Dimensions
3937.01,4222.44 to 12480.32,4212.6 on Mechanical 1
3927.17,4232.28 to 3927.17,9547.24 on Mechanical 1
